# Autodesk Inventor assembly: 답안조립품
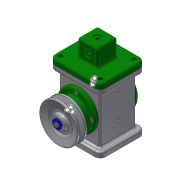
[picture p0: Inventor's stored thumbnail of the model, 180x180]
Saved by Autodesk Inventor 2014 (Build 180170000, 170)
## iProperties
Created: 2017-08
Part Number: 답안조립품
Document SubType Name: Assembly
Designer: user
Author: user
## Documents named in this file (18)
- C:\Users\user\Desktop\470808V1001\답안조립품.iam
- C:\Users\user\Desktop\470808V1001\본체.ipt
- C:\Users\user\Desktop\470808V1001\편심축.ipt
- C:\Users\user\Desktop\470808V1001\키 4 x 4 x 12.ipt
- C:\Users\user\Desktop\470808V1001\V-벨트풀리.ipt
- C:\Users\user\Desktop\470808V1001\와셔 4x16.ipt
- C:\Users\user\Desktop\470808V1001\볼트 M4 x 10.ipt
- C:\Users\user\Desktop\470808V1001\베어링 17 x 40 x 12.ipt
- C:\Users\user\Desktop\470808V1001\링크.ipt
- C:\Users\user\Desktop\470808V1001\슬라이더.ipt
- C:\Users\user\Desktop\470808V1001\클레비스 핀 6 x 22.ipt
- 클레비스 핀 6 x 22.ipt
- C:\Users\user\Desktop\470808V1001\앞커버.ipt
- C:\Users\user\Desktop\470808V1001\오일 실 17 30 8.ipt
- C:\Users\user\Desktop\470808V1001\뒤커버.ipt
- C:\Users\user\Desktop\470808V1001\덮개.ipt
- C:\Users\user\Desktop\470808V1001\볼트 M4 x 8.ipt
- C:\Users\user\Desktop\470808V1001\E-링.ipt
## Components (2 placed, 2 different names)
1. V-벨트풀리:1
2. E-링:1 — 각도:2
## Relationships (1: Angle 1)
- 각도:2 [Angle]: E-링:1
